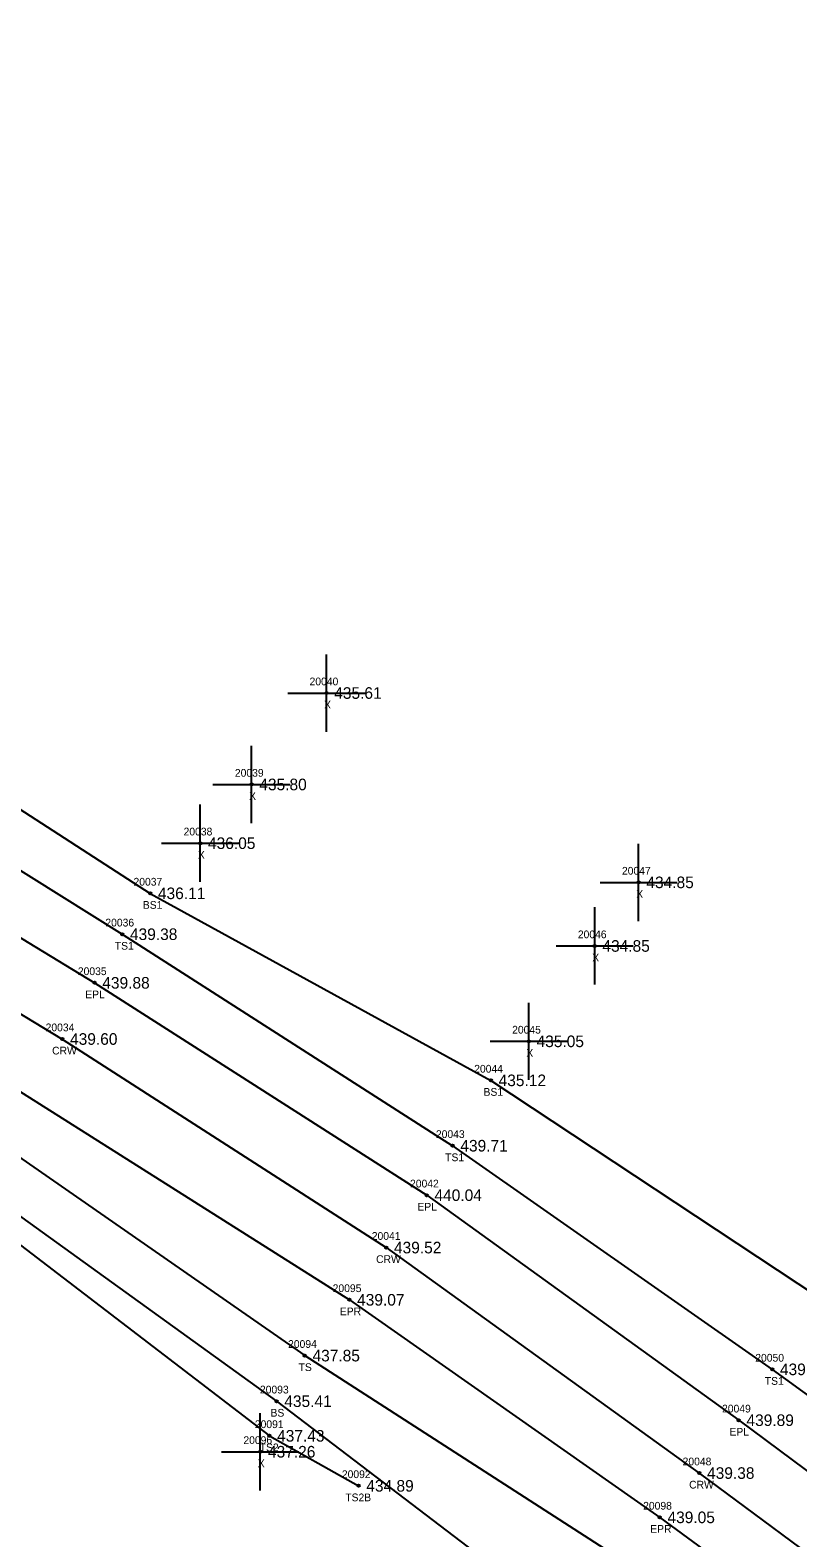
# Model space of a CAD drawing. Extents: x 1613836 to 1615109, y 777151 to 778248.
# Drawn here: x 1614083 to 1614182.4, y 777918.3 to 778113.4 of the extents above; entities that cross this region are included whole.
import ezdxf

# ---------------------------------------------------------------- set-up
doc = ezdxf.new("R2010")
doc.units = 0
for name, color, linetype in [('RD_DTM_BkLn1', 7, 'Continuous'), ('RD_DTM_BkLn2', 7, 'Continuous'), ('RD_DTM_BkLn_txCode', 7, 'Continuous'), ('RD_EX_Misc', 7, 'Continuous'), ('RD_EX_Misc_txCode', 7, 'Continuous'), ('RD_EX_Road', 7, 'Continuous'), ('RD_EX_Road_txCode', 7, 'Continuous'), ('RD_EX_TX_Misc_ELEV', 7, 'Continuous'), ('RD_EX_TX_Road_ELEV', 7, 'Continuous'), ('RD_HC_Survey_ELEV', 7, 'Continuous'), ('RD_HC_Survey_txCode', 7, 'Continuous'), ('RD_SMD_Locator', 7, 'Continuous')]:
    doc.layers.add(name, color=color, linetype=linetype)

msp = doc.modelspace()

# ---------------------------------------------------------------- linework, layer by layer
at = {"layer": 'RD_DTM_BkLn1'}
msp.add_lwpolyline([(1613865.21, 778095.86), (1613910.73, 778075.92), (1613956.18, 778054.99), (1614000.73, 778032.51), (1614044.52, 778008.68), (1614087.21, 777982.81), (1614129.12, 777955.82), (1614169.63, 777926.64), (1614209.9, 777896.76), (1614249.35, 777866.21), (1614288.43, 777835.55), (1614366.39, 777772.65), (1614443.98, 777709.72)], dxfattribs=at)
at = {"layer": 'RD_DTM_BkLn2'}
for points in [[(1613872.63, 778113.36), (1613919.46, 778094.34), (1613965.43, 778074.52), (1614011.49, 778053.16), (1614057.96, 778027.92), (1614098.58, 778001.66), (1614142.66, 777977.46), (1614185.05, 777949.4), (1614203.81, 777935.88)], [(1613870.65, 778107.91), (1613917.36, 778089.81), (1613963.47, 778068.53), (1614008.76, 778046.32), (1614052.42, 778023.01), (1614094.96, 777996.37), (1614137.71, 777969), (1614179.06, 777940.06), (1614196.49, 777927.41), (1614202.23, 777922.93), (1614210.94, 777920.91), (1614226.4, 777922.61), (1614267.62, 777889.85), (1614307.16, 777859.76), (1614381.32, 777790.21), (1614451.43, 777721.4), (1614453.49, 777722.08), (1614455.33, 777720.48), (1614437.07, 777696.16)], [(1613860.36, 778083.39), (1613904.96, 778062.9), (1613950.73, 778042.94), (1613994.86, 778021.25), (1614038.25, 777997.65), (1614118.58, 777941.84), (1614160.54, 777914.82), (1614182.29, 777896.21), (1614189.42, 777895.9), (1614196.65, 777882.72), (1614195.5, 777875.76), (1614231.56, 777844.86), (1614271.92, 777815.6), (1614305.89, 777789.49), (1614313.92, 777782.98), (1614351.2, 777751.93), (1614424.47, 777701.24), (1614433.25, 777695.63), (1614437.07, 777696.16)], [(1613858.47, 778079.63), (1613903.77, 778059.57), (1613949.1, 778039.22), (1613993.41, 778017.95), (1614036.6, 777992.42), (1614114.93, 777935.94), (1614154.39, 777905.9), (1614174.38, 777888.71)], [(1613854.82, 778071.61), (1613898.38, 778053.14), (1613944.64, 778032.38), (1613990.37, 778013.08), (1614032.71, 777987.43), (1614072.91, 777962.89), (1614114, 777931.46), (1614125.54, 777924.99)]]:
    msp.add_lwpolyline(points, dxfattribs=at)
at = {"layer": 'RD_EX_Misc'}
for p, q in [((1614121.39, 778022.58), (1614121.39, 778032.58)), ((1614116.39, 778027.58), (1614126.39, 778027.58)), ((1614111.7, 778010.75), (1614111.7, 778020.75)), ((1614106.7, 778015.75), (1614116.7, 778015.75)), ((1614105.06, 778003.15), (1614105.06, 778013.15)), ((1614100.06, 778008.15), (1614110.06, 778008.15)), ((1614161.78, 777998.08), (1614161.78, 778008.08)), ((1614156.78, 778003.08), (1614166.78, 778003.08)), ((1614156.09, 777989.85), (1614156.09, 777999.85)), ((1614151.09, 777994.85), (1614161.09, 777994.85)), ((1614147.57, 777977.51), (1614147.57, 777987.51)), ((1614142.57, 777982.51), (1614152.57, 777982.51)), ((1614112.82, 777924.4), (1614112.82, 777934.4)), ((1614107.82, 777929.4), (1614117.82, 777929.4))]:
    msp.add_line(p, q, dxfattribs=at)
at = {"layer": 'RD_EX_Road'}
for points in [[(1613868.87, 778104.15), (1613915.02, 778083.82), (1613960.16, 778062.2), (1614004.58, 778040.28), (1614048.84, 778015.98), (1614091.38, 777990.08), (1614134.36, 777962.6), (1614174.73, 777933.48), (1614192.07, 777920.58), (1614215.93, 777904.23), (1614254.59, 777873.05), (1614293.82, 777842.42), (1614371.74, 777779.59), (1614449.33, 777716.3), (1614443.98, 777709.72), (1614439.38, 777704.09)], [(1613862.14, 778087.92), (1613908.12, 778068.22), (1613952.96, 778047.38), (1613997, 778025.09), (1614041.16, 778001.63), (1614124.35, 777949.06), (1614164.51, 777920.91), (1614187.11, 777904.29), (1614205.27, 777889.82), (1614244.49, 777859.52), (1614283.42, 777829.45), (1614361.06, 777765.89), (1614439.38, 777704.09)]]:
    msp.add_lwpolyline(points, dxfattribs=at)
at = {"layer": 'RD_SMD_Locator'}
for centre in [(1614121.39, 778027.58), (1614111.7, 778015.75), (1614105.06, 778008.15), (1614161.78, 778003.08), (1614098.58, 778001.66), (1614094.96, 777996.37), (1614156.09, 777994.85), (1614091.38, 777990.08), (1614087.21, 777982.81), (1614147.57, 777982.51), (1614142.66, 777977.46), (1614137.71, 777969), (1614134.36, 777962.6), (1614129.12, 777955.82), (1614124.35, 777949.06), (1614118.58, 777941.84), (1614179.06, 777940.06), (1614114.93, 777935.94), (1614174.73, 777933.48), (1614114, 777931.46), (1614112.82, 777929.4), (1614169.63, 777926.64), (1614125.54, 777924.99), (1614164.51, 777920.91)]:
    msp.add_circle(centre, 0.15, dxfattribs=at)

# ---------------------------------------------------------------- texts
at = {"layer": 'RD_DTM_BkLn_txCode'}
for s, p in [('20037', (1614096.42, 778002.66)), ('BS1', (1614097.63, 777999.66)), ('20036', (1614092.78, 777997.37)), ('TS1', (1614094, 777994.37)), ('20044', (1614140.5, 777978.46)), ('BS1', (1614141.71, 777975.46)), ('20043', (1614135.55, 777970)), ('TS1', (1614136.74, 777967)), ('20094', (1614116.42, 777942.84)), ('20050', (1614176.87, 777941.06)), ('TS', (1614117.78, 777939.84)), ('20093', (1614112.78, 777936.94)), ('TS1', (1614178.1, 777938.06)), ('BS', (1614114.15, 777933.94)), ('20091', (1614112.12, 777932.46)), ('TS2', (1614112.75, 777929.46)), ('20092', (1614123.38, 777925.99)), ('TS2B', (1614123.82, 777922.99))]:
    msp.add_text(s, height=1, dxfattribs=at).set_placement(p)
at = {"layer": 'RD_EX_Misc_txCode'}
for s, p in [('20040', (1614119.2, 778028.58)), ('X', (1614121.08, 778025.58)), ('20039', (1614109.54, 778016.75)), ('X', (1614111.38, 778013.75)), ('20038', (1614102.9, 778009.15)), ('X', (1614104.75, 778006.15)), ('20047', (1614159.62, 778004.08)), ('X', (1614161.47, 778001.08)), ('20046', (1614153.91, 777995.85)), ('X', (1614155.78, 777992.85)), ('20045', (1614145.41, 777983.51)), ('X', (1614147.25, 777980.51)), ('20096', (1614110.64, 777930.4)), ('X', (1614112.5, 777927.4))]:
    msp.add_text(s, height=1, dxfattribs=at).set_placement(p)
at = {"layer": 'RD_EX_Road_txCode'}
for s, p in [('20035', (1614089.22, 777991.08)), ('EPL', (1614090.18, 777988.08)), ('20042', (1614132.2, 777963.6)), ('EPL', (1614133.15, 777960.6)), ('20095', (1614122.19, 777950.06)), ('EPR', (1614123.12, 777947.06)), ('20049', (1614172.57, 777934.48)), ('EPL', (1614173.53, 777931.48)), ('20098', (1614162.36, 777921.91)), ('EPR', (1614163.28, 777918.91))]:
    msp.add_text(s, height=1, dxfattribs=at).set_placement(p)
at = {"layer": 'RD_EX_TX_Misc_ELEV'}
for s, p in [('435.61', (1614122.39, 778026.83)), ('435.80', (1614112.7, 778015)), ('436.05', (1614106.06, 778007.4)), ('436.11', (1614099.58, 778000.91)), ('434.85', (1614162.78, 778002.33)), ('439.38', (1614095.96, 777995.62)), ('434.85', (1614157.09, 777994.1)), ('435.05', (1614148.57, 777981.76)), ('435.12', (1614143.66, 777976.71)), ('439.71', (1614138.71, 777968.25)), ('437.85', (1614119.58, 777941.09)), ('439.59', (1614180.06, 777939.31)), ('435.41', (1614115.93, 777935.19)), ('437.43', (1614115, 777930.71)), ('437.26', (1614113.82, 777928.65)), ('434.89', (1614126.54, 777924.24))]:
    msp.add_text(s, height=1.5, dxfattribs=at).set_placement(p)
at = {"layer": 'RD_EX_TX_Road_ELEV'}
for s, p in [('439.88', (1614092.38, 777989.33)), ('440.04', (1614135.36, 777961.85)), ('439.07', (1614125.35, 777948.31)), ('439.89', (1614175.73, 777932.73)), ('439.05', (1614165.51, 777920.16))]:
    msp.add_text(s, height=1.5, dxfattribs=at).set_placement(p)
at = {"layer": 'RD_HC_Survey_ELEV'}
for s, p in [('439.60', (1614088.21, 777982.06)), ('439.52', (1614130.12, 777955.07)), ('439.38', (1614170.63, 777925.89))]:
    msp.add_text(s, height=1.5, dxfattribs=at).set_placement(p)
at = {"layer": 'RD_HC_Survey_txCode'}
for s, p in [('20034', (1614085.05, 777983.81)), ('CRW', (1614085.89, 777980.81)), ('20041', (1614127.25, 777956.82)), ('CRW', (1614127.81, 777953.82)), ('20048', (1614167.47, 777927.64)), ('CRW', (1614168.31, 777924.64))]:
    msp.add_text(s, height=1, dxfattribs=at).set_placement(p)

doc.saveas('drawing.dxf')
